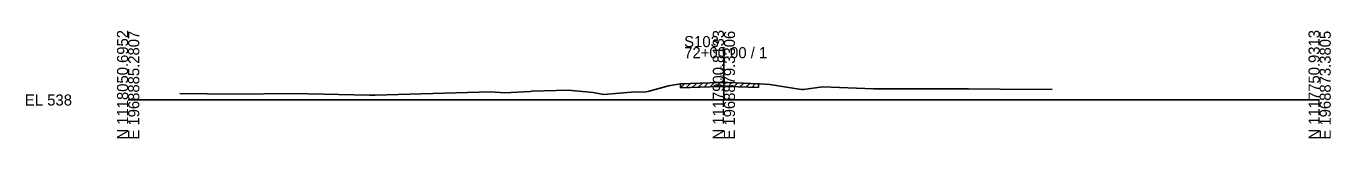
# Model space of a CAD drawing. Extents: x 974 to 1303, y 990 to 14518.
# Drawn here: x 974.3 to 1302.8, y 12490.3 to 12517.5 of the extents above; entities that cross this region are included whole.
import ezdxf

# ---------------------------------------------------------------- set-up
doc = ezdxf.new("R2010")
doc.units = 0
for name, color, linetype in [('Level 10', 7, 'Continuous'), ('Level 60', 7, 'Continuous'), ('Level 61', 7, 'Continuous'), ('Level 63', 7, 'Continuous')]:
    doc.layers.add(name, color=color, linetype=linetype)

msp = doc.modelspace()

# ---------------------------------------------------------------- linework, layer by layer
at = {"layer": 'Level 60'}
for p, q in [((1136.07, 12503.62), (1138.61, 12503.99)), ((1138.61, 12503.99), (1139.04, 12504.05)), ((1139.04, 12504.05), (1148.98, 12504.41)), ((1148.98, 12504.41), (1150.11, 12504.45)), ((1150.11, 12504.45), (1150.97, 12504.42)), ((1150.97, 12504.42), (1158.68, 12504.12)), ((1158.68, 12504.12), (1158.98, 12504.11)), ((1158.98, 12504.11), (1161.57, 12503.95)), ((1161.57, 12503.95), (1168.95, 12502.75)), ((1013.04, 12501.68), (1026.78, 12501.48)), ((1026.78, 12501.48), (1041.5, 12501.64)), ((1041.5, 12501.64), (1060.81, 12501.19)), ((1060.81, 12501.19), (1061.35, 12501.18)), ((1061.35, 12501.18), (1062.18, 12501.22)), ((1062.18, 12501.22), (1091.21, 12502.03)), ((1091.21, 12502.03), (1094.86, 12501.84)), ((1094.86, 12501.84), (1101.25, 12502.17)), ((1101.25, 12502.17), (1101.64, 12502.19)), ((1101.64, 12502.19), (1110.81, 12502.5)), ((1110.81, 12502.5), (1117.07, 12501.92)), ((1117.07, 12501.92), (1119.76, 12501.37)), ((1119.76, 12501.37), (1127.64, 12502.1)), ((1127.64, 12502.1), (1129.9, 12501.96)), ((1129.9, 12501.96), (1130.82, 12502.17)), ((1130.82, 12502.17), (1134.54, 12503.2)), ((1134.54, 12503.2), (1136.07, 12503.62)), ((1168.95, 12502.75), (1169.63, 12502.63)), ((1169.63, 12502.63), (1170.04, 12502.69)), ((1170.04, 12502.69), (1174.84, 12503.3)), ((1174.84, 12503.3), (1187.69, 12502.78)), ((1187.69, 12502.78), (1211.63, 12502.83)), ((1211.63, 12502.83), (1219.6, 12502.73)), ((1219.6, 12502.73), (1232.63, 12502.68))]:
    msp.add_line(p, q, dxfattribs=at)
at = {"layer": 'Level 61'}
for p, q in [((1139.04, 12503.05), (1140.08, 12504.08)), ((1139.04, 12503.05), (1139.04, 12504.05)), ((1140.54, 12503.1), (1141.58, 12504.14)), ((1142.04, 12503.16), (1143.08, 12504.2)), ((1143.54, 12503.21), (1144.58, 12504.25)), ((1145.04, 12503.27), (1146.08, 12504.31)), ((1146.54, 12503.32), (1147.58, 12504.36)), ((1148.04, 12503.38), (1149.08, 12504.42)), ((1149.54, 12503.43), (1150.54, 12504.44)), ((1151.04, 12503.42), (1152, 12504.38)), ((1152.54, 12503.36), (1153.5, 12504.32)), ((1154.04, 12503.3), (1155, 12504.27)), ((1155.54, 12503.24), (1156.5, 12504.21)), ((1157.04, 12503.19), (1158, 12504.15)), ((1158.68, 12504.12), (1158.68, 12503.12)), ((1139.04, 12503.05), (1148.98, 12503.41)), ((1148.98, 12503.41), (1150.11, 12503.45)), ((1150.11, 12503.45), (1150.97, 12503.42)), ((1150.97, 12503.42), (1158.68, 12503.12)), ((1158.68, 12503.12), (1158.68, 12503.12))]:
    msp.add_line(p, q, dxfattribs=at)
at = {"layer": 'Level 63'}
for p, q in [((1150, 12500), (1150, 12513.36)), ((1000, 12500), (1150, 12500)), ((1150, 12500), (1300, 12500))]:
    msp.add_line(p, q, dxfattribs=at)

# ---------------------------------------------------------------- texts
at = {"layer": 'Level 10'}
msp.add_text('542.45', height=0.9, rotation=90, dxfattribs=at).set_placement((1149.95, 12504.95))
at = {"layer": 'Level 63'}
for s, p in [('N 1118050.6952', (1000, 12490)), ('E 1968885.2807', (1002.8, 12490)), ('N 1117900.8133', (1150, 12490)), ('E 1968879.3306', (1152.8, 12490)), ('N 1117750.9313', (1300, 12490)), ('E 1968873.3805', (1302.8, 12490))]:
    msp.add_text(s, height=2.8, rotation=90, dxfattribs=at).set_placement(p)
for s, p in [('S103', (1140, 12513.36)), ('72+00.00 / 1', (1140, 12510.56)), ('EL 538', (974, 12498.6))]:
    msp.add_text(s, height=2.8, dxfattribs=at).set_placement(p)

doc.saveas('drawing.dxf')
